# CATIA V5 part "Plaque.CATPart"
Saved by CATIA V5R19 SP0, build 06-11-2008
Part number: Plaque
Publications: "L", "e", "a", "La"
Bounding box of the stored display mesh (mm): x 0 to 300, y -80 to 80, z 0 to 12
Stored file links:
  G:\EU_thinkMotion\CFAO_2010\MMS_groupe3\MMS_groupe3\A reprendre\evulliez\evulliez\Plaque.CATPart
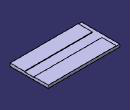
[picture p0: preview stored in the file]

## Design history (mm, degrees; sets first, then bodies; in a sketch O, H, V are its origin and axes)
Parameters
  L = 300 mm
  La = 160 mm
  e = 10 mm
  a = 40 mm
Body1 (main body)
  Sketch1 on xy-plane, origin (0, 0, 0), H (1, 0, 0), V (0, 1, 0)
    point P1 (0, -80)
    line L1 (0, -80) -> (300, -80)
    line L2 (300, -80) -> (300, 80)
    line L3 (300, 80) -> (0, 80)
    line L4 (0, 80) -> (0, -80)
    length L1 = 300 {= L}
    length L2 = 160 {= La}
    distance H L1 = 80 {= (La)/2}
    coincidence: P1 V
    horizontal: L1 H, L3 H
    vertical: L2 V, L4 V
  Pad1: profile Sketch1, direction (0, 0, 1), length 12 {= e+2mm}
  Sketch2 on end face of Pad1, origin (0, 0, 12), H (1, 0, 0), V (0, 1, 0)
    line L1 (300, 20) -> (300, -20)
    line L2 (0, -80) -> (0, 80)
    point P3 (0, -80)
    line L3 (0, 80) -> (15, 80)
    line L4 (15, 80) -> (15, 20)
    line L5 (15, 20) -> (300, 20)
    line L6 (300, -20) -> (15, -20)
    point P7 (15, -20)
    line L7 (15, -20) -> (15, -80)
    line L8 (0, -80) -> (15, -80)
    length L1 = 40 {= a}
    length L2 = 160 {= La}
    distance H L5 = 20 {= a /2}
    length L3 = 15
    distance H L8 = 80 {= La /2}
    distance L1 L2 = 300 {= L}
    vertical: L1 V, L2 V, L4 V, L7 V
    coincidence: P3 V, P7 L4
    horizontal: L3 H, L5 H, L6 H, L8 H
  Pocket1: profile Sketch2, direction (0, 0, -1), length 2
